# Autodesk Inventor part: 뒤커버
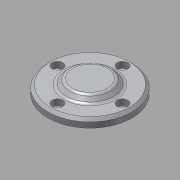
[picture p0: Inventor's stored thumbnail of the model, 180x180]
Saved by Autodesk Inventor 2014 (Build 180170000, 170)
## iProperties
Created: 2015-09
Part Number: 뒤커버
Material: 알루미늄 6061
Document SubType Name: Modeling
Designer: mduedu
Density: 1 g/cm^3
Appearance: 알루미늄 - 평지
Author: mduedu
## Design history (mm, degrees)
sketch "스케치1"
  geometry: L1 (0, 7.5)-(0, -7.5); L2 (0, 7.5)-(14, 7.5); L3 (14, 7.5)-(18, 3.5); L4 (18, 3.5)-(31, 3.5); L5 (31, 3.5)-(31, -2.5); L6 (31, -2.5)-(17.5, -2.5); L7 (17.5, -2.5)-(17.5, -7.5); L8 (17.5, -7.5)-(0, -7.5); 2 further points
  constraints: 16 end point, 3 parallel, 2 perpendicular, 1 coincident, 1 horizontal, 1 midpoint, 1 vertical
  dimensions: "d0" = 15 distance of L1.start L1.end; "d1" = 4 distance between parallel lines of L4 L2; "d2" = 6 distance of L4.end L5.end; "d3" = 36 diameter of L3.end L1; "d4" = 35 diameter of L7 L1; "d5" = 62 diameter of L5 L1; "d7" = 45 deg angle of L3 L5
revolve "회전1" sketch "스케치1" stored, may be unused: angle "d8" = 90 deg
hole "구멍1" diameter "d11" = 24; stored, may be unused: countersink angle "d15" = 90 deg, drill point angle "d17" = 0 deg; dims "d9" = 10, "d10" = 10, "d12" = 6, "d13" = 4, "d14" = 2, "d16" = 8
fillet "모깎기1" dims "d18" = 3
chamfer "모따기1" distance "d19" = 1; stored, may be unused: second distance "d20" = 2, angle "d21" = 45 deg
chamfer "모따기2" distance "d22" = 2; stored, may be unused: second distance "d23" = 2, angle "d24" = 45 deg
fillet "모깎기2" dims "d25" = 3
fillet "모깎기3" dims "d26" = 3
sketch "스케치2" dims "d27" = 48
  geometry: 6 further points
  constraints: 2 vertical alignment, 1 coincident, 7 other
  dimensions: "d33" = 360 deg dimension on point (0, 0) point (0, 24) (derived)
sketch "스케치3"
  geometry: 4 further points
hole "구멍2" sketch "스케치3" at (-24, 0), (0, -24), (24, 0), (0, 24) diameter "d35" = 4.5; stored, may be unused: countersink angle "d39" = 90 deg, drill point angle "d41" = 0 deg; dims "d36" = 6, "d37" = 8, "d38" = 4.6, "d40" = 8
node "솔리드1"
